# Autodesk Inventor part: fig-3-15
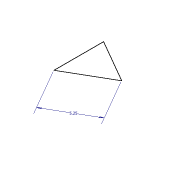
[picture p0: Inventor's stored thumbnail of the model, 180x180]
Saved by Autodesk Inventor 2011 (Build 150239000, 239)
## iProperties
Created: 2009-11
Part Number: fig-3-15
Document SubType Name: Modeling
Designer: Sham
Density: 1 g/cm^3
Author: Sham
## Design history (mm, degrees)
sketch "Sketch1"
  geometry: L1 (0.077, -0.115)-(0.077, -5.365); L2 (0.077, -5.365)-(4.624, -2.74); L3 (4.624, -2.74)-(0.077, -0.115)
  constraints: 6 end point, 2 equal length, 1 vertical
  dimensions: "d1" = 5.25 dimension on L1.start L1.end L1 L2.end L2 L3; "d1" = 5.25 distance of L1.end L2.end
